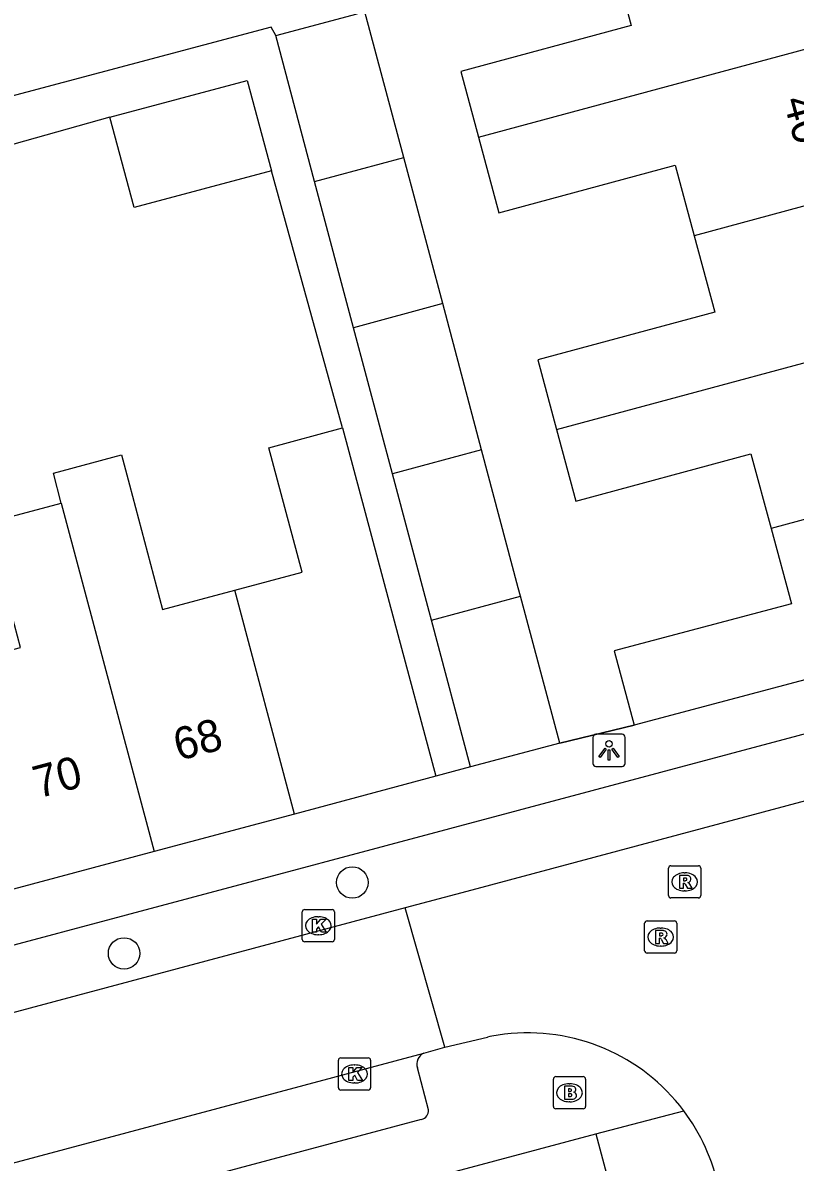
# Model space of a CAD drawing. Extents: x 162542 to 163144, y 380786 to 381511.
# Drawn here: x 162893.88 to 162917.88, y 381087.73 to 381123.11 of the extents above; entities that cross this region are included whole.
import ezdxf

# ---------------------------------------------------------------- set-up
doc = ezdxf.new("R2010")
doc.units = 0
for name, color, linetype in [('IMGEO_Boom', 7, 'Continuous'), ('IMGEO_Brandkraan', 7, 'Continuous'), ('IMGEO_Kolk', 7, 'Continuous'), ('IMGEO_Lichtpunt', 7, 'Continuous'), ('IMGEO_Muur', 7, 'Continuous'), ('IMGEO_Pand', 7, 'Continuous'), ('IMGEO_Pand_nummerreeks', 7, 'Continuous'), ('IMGEO_Rijbaan_lokaal_open', 7, 'Continuous'), ('IMGEO_Rioolput', 7, 'Continuous'), ('IMGEO_Voetpad_open', 7, 'Continuous')]:
    doc.layers.add(name, color=color, linetype=linetype)

msp = doc.modelspace()

# ---------------------------------------------------------------- linework, layer by layer
at = {"layer": 'IMGEO_Boom'}
for centre in [(162904.119, 381096.414), (162897.031, 381094.211)]:
    msp.add_circle(centre, 0.489, dxfattribs=at)
at = {"layer": 'IMGEO_Brandkraan'}
for p, q in [((162910.364, 381089.46), (162910.364, 381090.312)), ((162910.439, 381090.386), (162911.291, 381090.386)), ((162911.365, 381090.312), (162911.365, 381089.46)), ((162910.852, 381090.166), (162910.877, 381090.166)), ((162910.875, 381089.606), (162910.85, 381089.606)), ((162911.291, 381089.386), (162910.439, 381089.386))]:
    msp.add_line(p, q, dxfattribs=at)
for points in [[(162910.364, 381089.46), (162910.364, 381090.312)], [(162910.439, 381090.386), (162911.291, 381090.386)], [(162911.365, 381090.312), (162911.365, 381089.46)], [(162910.712, 381090.086), (162910.712, 381089.686), (162910.925, 381089.686)], [(162910.943, 381090.086), (162910.712, 381090.086)], [(162910.891, 381090.005), (162910.837, 381090.005), (162910.837, 381089.929)], [(162910.837, 381089.929), (162910.89, 381089.929)], [(162910.899, 381089.853), (162910.837, 381089.853), (162910.837, 381089.772)], [(162910.837, 381089.772), (162910.899, 381089.772)], [(162911.291, 381089.386), (162910.439, 381089.386)]]:
    msp.add_lwpolyline(points, dxfattribs=at)
for centre, radius, start, end in [((162910.441, 381090.31), 0.0765, 91.552, 178.448), ((162910.441, 381090.31), 0.0765, 91.552, 178.448), ((162911.289, 381090.31), 0.0765, 1.552, 88.448), ((162911.289, 381090.31), 0.0765, 1.552, 88.448), ((162910.892, 381089.967), 0.0379, 267.8285, 90.9355), ((162910.947, 381089.941), 0.145, 59.4692, 91.5367), ((162910.972, 381089.988), 0.0922, 285.5137, 58.1501), ((162910.9, 381089.812), 0.0404, 269.8759, 90.5077), ((162910.931, 381089.937), 0.251, 268.6676, 293.5347), ((162910.977, 381089.796), 0.105, 301.3115, 78.989), ((162910.441, 381089.462), 0.0765, 181.552, 268.448), ((162910.441, 381089.462), 0.0765, 181.552, 268.448), ((162911.289, 381089.462), 0.0765, 271.552, 358.448), ((162911.289, 381089.462), 0.0765, 271.552, 358.448)]:
    msp.add_arc(centre, radius, start, end, dxfattribs=at)
for centre, major_axis, ratio, start_param, end_param in [((162910.851, 381089.886), (-0.387, 0.002), 0.722429, 4.712389, 7.853982), ((162910.876, 381089.886), (-0.39, 0.002), 0.717154, 1.570796, 4.712389)]:
    msp.add_ellipse(centre, major_axis=major_axis, ratio=ratio, start_param=start_param, end_param=end_param, dxfattribs=at)
at = {"layer": 'IMGEO_Kolk'}
for p, q in [((162902.565, 381094.647), (162902.565, 381095.499)), ((162902.64, 381095.573), (162903.492, 381095.573)), ((162903.053, 381095.353), (162903.078, 381095.353)), ((162903.566, 381095.499), (162903.566, 381094.647)), ((162903.492, 381094.573), (162902.64, 381094.573)), ((162903.076, 381094.793), (162903.051, 381094.793)), ((162903.688, 381090.043), (162903.688, 381090.895)), ((162903.763, 381090.969), (162904.615, 381090.969)), ((162904.176, 381090.749), (162904.201, 381090.749)), ((162904.689, 381090.895), (162904.689, 381090.043)), ((162904.615, 381089.969), (162903.763, 381089.969)), ((162904.199, 381090.189), (162904.174, 381090.189))]:
    msp.add_line(p, q, dxfattribs=at)
for points in [[(162902.565, 381094.647), (162902.565, 381095.499)], [(162902.64, 381095.573), (162903.492, 381095.573)], [(162902.886, 381095.273), (162903.009, 381095.273), (162903.009, 381095.122), (162903.139, 381095.273), (162903.303, 381095.273), (162903.157, 381095.122), (162903.31, 381094.873), (162903.158, 381094.873), (162903.073, 381095.037), (162903.009, 381094.97), (162903.009, 381094.873), (162902.886, 381094.873), (162902.886, 381095.273)], [(162903.566, 381095.499), (162903.566, 381094.647)], [(162903.492, 381094.573), (162902.64, 381094.573)], [(162903.688, 381090.043), (162903.688, 381090.895)], [(162903.763, 381090.969), (162904.615, 381090.969)], [(162904.009, 381090.669), (162904.132, 381090.669), (162904.132, 381090.518), (162904.262, 381090.669), (162904.426, 381090.669), (162904.28, 381090.518), (162904.433, 381090.269), (162904.281, 381090.269), (162904.196, 381090.433), (162904.132, 381090.366), (162904.132, 381090.269), (162904.009, 381090.269), (162904.009, 381090.669)], [(162904.689, 381090.895), (162904.689, 381090.043)], [(162904.615, 381089.969), (162903.763, 381089.969)]]:
    msp.add_lwpolyline(points, dxfattribs=at)
for centre, start, end in [((162902.642, 381095.497), 91.552, 178.448), ((162902.642, 381095.497), 91.552, 178.448), ((162903.49, 381095.497), 1.552, 88.448), ((162903.49, 381095.497), 1.552, 88.448), ((162902.642, 381094.649), 181.552, 268.448), ((162902.642, 381094.649), 181.552, 268.448), ((162903.49, 381094.649), 271.552, 358.448), ((162903.49, 381094.649), 271.552, 358.448), ((162903.765, 381090.893), 91.552, 178.448), ((162903.765, 381090.893), 91.552, 178.448), ((162904.613, 381090.893), 1.552, 88.448), ((162904.613, 381090.893), 1.552, 88.448), ((162903.765, 381090.045), 181.552, 268.448), ((162903.765, 381090.045), 181.552, 268.448), ((162904.613, 381090.045), 271.552, 358.448), ((162904.613, 381090.045), 271.552, 358.448)]:
    msp.add_arc(centre, 0.0765, start, end, dxfattribs=at)
for centre, major_axis, ratio, start_param, end_param in [((162903.052, 381095.073), (-0.387, 0.002), 0.722429, 4.712389, 7.853982), ((162903.077, 381095.073), (-0.39, 0.002), 0.717154, 1.570796, 4.712389), ((162904.175, 381090.469), (-0.387, 0.002), 0.722429, 4.712389, 7.853982), ((162904.2, 381090.469), (-0.39, 0.002), 0.717154, 1.570796, 4.712389)]:
    msp.add_ellipse(centre, major_axis=major_axis, ratio=ratio, start_param=start_param, end_param=end_param, dxfattribs=at)
at = {"layer": 'IMGEO_Lichtpunt'}
for p, q in [((162911.594, 381100.921), (162911.594, 381100.114)), ((162911.594, 381100.921), (162911.594, 381100.114)), ((162912.496, 381101.016), (162911.688, 381101.016)), ((162912.496, 381101.016), (162911.688, 381101.016)), ((162912.59, 381100.114), (162912.59, 381100.921)), ((162912.59, 381100.114), (162912.59, 381100.921)), ((162911.688, 381100.02), (162912.496, 381100.02)), ((162911.688, 381100.02), (162912.496, 381100.02))]:
    msp.add_line(p, q, dxfattribs=at)
for points in [[(162911.968, 381100.585), (162912.007, 381100.557), (162911.819, 381100.295), (162911.781, 381100.322), (162911.968, 381100.585)], [(162912.18, 381100.557), (162912.218, 381100.584), (162912.405, 381100.322), (162912.366, 381100.294), (162912.18, 381100.557)], [(162912.07, 381100.537), (162912.117, 381100.537), (162912.117, 381100.215), (162912.07, 381100.215), (162912.07, 381100.537)]]:
    msp.add_lwpolyline(points, dxfattribs=at)
msp.add_circle((162912.093, 381100.719), 0.0994, dxfattribs=at)
for centre, start, end in [((162911.688, 381100.921), 90, 180), ((162911.688, 381100.921), 90, 180), ((162912.496, 381100.921), 0, 90), ((162912.496, 381100.921), 0, 90), ((162911.688, 381100.114), 180, 270), ((162911.688, 381100.114), 180, 270), ((162912.496, 381100.114), 270, 0), ((162912.496, 381100.114), 270, 360)]:
    msp.add_arc(centre, 0.0946, start, end, dxfattribs=at)
at = {"layer": 'IMGEO_Muur'}
msp.add_lwpolyline([(162910.56, 381100.744), (162912.873, 381101.295)], dxfattribs=at)
at = {"layer": 'IMGEO_Pand'}
for points in [[(162912.087, 381125.607), (162912.783, 381123.027), (162907.49, 381121.599), (162908.042, 381119.555)], [(162901.741, 381122.714), (162904.267, 381123.387)], [(162905.717, 381118.928), (162904.512, 381123.452), (162904.267, 381123.387)], [(162902.948, 381118.181), (162901.741, 381122.714)], [(162908.042, 381119.555), (162920.256, 381122.851)], [(162896.588, 381120.178), (162900.859, 381121.319), (162901.61, 381118.51)], [(162901.61, 381118.51), (162897.339, 381117.369), (162896.588, 381120.178)], [(162908.042, 381119.555), (162908.674, 381117.211), (162914.145, 381118.687), (162914.736, 381116.495)], [(162902.948, 381118.181), (162905.717, 381118.928)], [(162906.926, 381114.388), (162905.717, 381118.928)], [(162921.471, 381118.312), (162914.736, 381116.495)], [(162904.158, 381113.641), (162902.948, 381118.181)], [(162914.736, 381116.495), (162915.375, 381114.126), (162909.881, 381112.644), (162910.466, 381110.476)], [(162906.926, 381114.388), (162904.158, 381113.641)], [(162908.136, 381109.847), (162906.926, 381114.388)], [(162910.466, 381110.476), (162922.685, 381113.774)], [(162905.367, 381109.1), (162904.158, 381113.641)], [(162900.475, 381105.495), (162902.557, 381106.051), (162901.525, 381109.915), (162903.813, 381110.528)], [(162903.813, 381110.528), (162905.419, 381104.542), (162906.714, 381099.712)], [(162910.466, 381110.476), (162911.065, 381108.254), (162916.502, 381109.721), (162917.127, 381107.407)], [(162908.136, 381109.847), (162905.367, 381109.1)], [(162909.345, 381105.308), (162909.275, 381105.569), (162908.136, 381109.847)], [(162895.082, 381108.194), (162894.834, 381109.127), (162896.948, 381109.69), (162897.197, 381108.759), (162898.229, 381104.895), (162900.475, 381105.495)], [(162906.576, 381104.561), (162906.504, 381104.831), (162905.367, 381109.1)], [(162923.9, 381109.234), (162917.127, 381107.407)], [(162891.746, 381103.164), (162893.813, 381103.716), (162892.781, 381107.58), (162895.082, 381108.194)], [(162895.082, 381108.194), (162897.964, 381097.375)], [(162917.127, 381107.407), (162917.759, 381105.065), (162912.25, 381103.604), (162912.873, 381101.295)], [(162902.328, 381098.541), (162900.475, 381105.495)], [(162906.576, 381104.561), (162909.345, 381105.308)], [(162910.56, 381100.744), (162909.345, 381105.308)], [(162907.791, 381100.001), (162906.576, 381104.561)], [(162925.15, 381104.562), (162912.873, 381101.295)], [(162910.56, 381100.744), (162907.791, 381100.001)], [(162906.714, 381099.712), (162902.328, 381098.541)], [(162902.328, 381098.541), (162897.964, 381097.375)], [(162897.964, 381097.375), (162893.599, 381096.209)], [(162907.185, 381087.409), (162909.899, 381088.134), (162911.688, 381088.611)], [(162911.688, 381088.611), (162914.576, 381077.79), (162915.089, 381075.867)]]:
    msp.add_lwpolyline(points, dxfattribs=at)
at = {"layer": 'IMGEO_Rijbaan_lokaal_open'}
for points in [[(162901.741, 381122.714), (162901.595, 381122.971), (162820.992, 381101.538), (162820.968, 381101.532)], [(162922.875, 381100.201), (162907.674, 381096.138), (162905.759, 381095.626)], [(162905.759, 381095.626), (162875.371, 381087.503), (162868.302, 381085.609)], [(162906.998, 381091.296), (162905.759, 381095.626)], [(162906.998, 381091.296), (162908.323, 381091.615)], [(162871.254, 381081.738), (162906.341, 381091.119)], [(162906.341, 381091.119), (162906.488, 381091.158), (162906.998, 381091.296)]]:
    msp.add_lwpolyline(points, dxfattribs=at)
for centre, radius, start, end in [((162909.574, 381085.696), 6.05, 36.8734, 96.8935), ((162909.636, 381085.321), 6.43, 97.0376, 101.7809), ((162909.561, 381085.69), 6.064, 11.7881, 36.8402)]:
    msp.add_arc(centre, radius, start, end, dxfattribs=at)
at = {"layer": 'IMGEO_Rioolput'}
for p, q in [((162913.942, 381096.007), (162913.942, 381096.859)), ((162914.017, 381096.933), (162914.869, 381096.933)), ((162914.43, 381096.713), (162914.455, 381096.713)), ((162914.943, 381096.859), (162914.943, 381096.007)), ((162914.453, 381096.153), (162914.428, 381096.153)), ((162914.869, 381095.933), (162914.017, 381095.933)), ((162913.198, 381094.295), (162913.198, 381095.147)), ((162913.273, 381095.221), (162914.125, 381095.221)), ((162913.686, 381095.001), (162913.711, 381095.001)), ((162914.199, 381095.147), (162914.199, 381094.295)), ((162914.125, 381094.221), (162913.273, 381094.221)), ((162913.709, 381094.441), (162913.684, 381094.441))]:
    msp.add_line(p, q, dxfattribs=at)
for points in [[(162913.942, 381096.007), (162913.942, 381096.859)], [(162914.017, 381096.933), (162914.869, 381096.933)], [(162914.943, 381096.859), (162914.943, 381096.007)], [(162914.531, 381096.631), (162914.279, 381096.633), (162914.279, 381096.233)], [(162914.279, 381096.233), (162914.403, 381096.233), (162914.403, 381096.395), (162914.414, 381096.395)], [(162914.457, 381096.552), (162914.403, 381096.552), (162914.403, 381096.471)], [(162914.403, 381096.471), (162914.455, 381096.471)], [(162914.461, 381096.366), (162914.532, 381096.233), (162914.672, 381096.233), (162914.607, 381096.359)], [(162914.869, 381095.933), (162914.017, 381095.933)], [(162913.198, 381094.295), (162913.198, 381095.147)], [(162913.273, 381095.221), (162914.125, 381095.221)], [(162913.787, 381094.919), (162913.535, 381094.921), (162913.535, 381094.521)], [(162914.199, 381095.147), (162914.199, 381094.295)], [(162913.535, 381094.521), (162913.659, 381094.521), (162913.659, 381094.683), (162913.67, 381094.683)], [(162913.713, 381094.84), (162913.659, 381094.84), (162913.659, 381094.759)], [(162913.659, 381094.759), (162913.711, 381094.759)], [(162913.717, 381094.654), (162913.788, 381094.521), (162913.928, 381094.521), (162913.863, 381094.647)], [(162914.125, 381094.221), (162913.273, 381094.221)]]:
    msp.add_lwpolyline(points, dxfattribs=at)
for centre, radius, start, end in [((162914.019, 381096.857), 0.0765, 91.552, 178.448), ((162914.019, 381096.857), 0.0765, 91.552, 178.448), ((162914.867, 381096.857), 0.0765, 1.552, 88.448), ((162914.867, 381096.857), 0.0765, 1.552, 88.448), ((162914.413, 381096.342), 0.0533, 26.0293, 88.6989), ((162914.439, 381096.66), 0.19, 274.7715, 282.9687), ((162914.463, 381096.456), 0.0964, 77.0061, 93.1865), ((162914.477, 381096.513), 0.0378, 276.6634, 79.6772), ((162914.53, 381096.521), 0.109, 350.3612, 89.416), ((162914.528, 381096.521), 0.112, 277.5842, 350.9817), ((162914.512, 381096.306), 0.108, 29.5134, 73.7905), ((162914.019, 381096.009), 0.0765, 181.552, 268.448), ((162914.019, 381096.009), 0.0765, 181.552, 268.448), ((162914.867, 381096.009), 0.0765, 271.552, 358.448), ((162914.867, 381096.009), 0.0765, 271.552, 358.448), ((162913.275, 381095.145), 0.0765, 91.552, 178.448), ((162913.275, 381095.145), 0.0765, 91.552, 178.448), ((162913.786, 381094.809), 0.109, 350.3612, 89.416), ((162914.123, 381095.145), 0.0765, 1.552, 88.448), ((162914.123, 381095.145), 0.0765, 1.552, 88.448), ((162913.669, 381094.63), 0.0533, 26.0293, 88.6989), ((162913.695, 381094.948), 0.19, 274.7715, 282.9687), ((162913.719, 381094.744), 0.0964, 77.0061, 93.1865), ((162913.733, 381094.801), 0.0378, 276.6634, 79.6772), ((162913.784, 381094.809), 0.112, 277.5842, 350.9817), ((162913.768, 381094.594), 0.108, 29.5134, 73.7905), ((162913.275, 381094.297), 0.0765, 181.552, 268.448), ((162913.275, 381094.297), 0.0765, 181.552, 268.448), ((162914.123, 381094.297), 0.0765, 271.552, 358.448), ((162914.123, 381094.297), 0.0765, 271.552, 358.448)]:
    msp.add_arc(centre, radius, start, end, dxfattribs=at)
for centre, major_axis, ratio, start_param, end_param in [((162914.429, 381096.433), (-0.387, 0.002), 0.722429, 4.712389, 7.853982), ((162914.454, 381096.433), (-0.39, 0.002), 0.717154, 1.570796, 4.712389), ((162913.685, 381094.721), (-0.387, 0.002), 0.722429, 4.712389, 7.853982), ((162913.71, 381094.721), (-0.39, 0.002), 0.717154, 1.570796, 4.712389)]:
    msp.add_ellipse(centre, major_axis=major_axis, ratio=ratio, start_param=start_param, end_param=end_param, dxfattribs=at)
at = {"layer": 'IMGEO_Voetpad_open'}
for points in [[(162896.588, 381120.178), (162882.812, 381116.307)], [(162903.813, 381110.528), (162901.61, 381118.51)], [(162829.44, 381077.293), (162857.097, 381084.74), (162857.529, 381083.089), (162861.656, 381084.179), (162861.251, 381085.851), (162866.655, 381087.296), (162874.876, 381089.481), (162907.148, 381098.095), (162922.391, 381102.163), (162922.875, 381100.201)], [(162912.873, 381101.295), (162910.56, 381100.744)], [(162907.791, 381100.001), (162906.714, 381099.712)], [(162906.484, 381089.358), (162906.142, 381090.654)], [(162911.688, 381088.611), (162914.414, 381089.326)], [(162872.337, 381079.995), (162906.267, 381089.06)]]:
    msp.add_lwpolyline(points, dxfattribs=at)
for centre, radius, start, end in [((162906.514, 381090.77), 0.39, 116.3668, 197.2955), ((162906.216, 381089.325), 0.27, 280.9696, 6.9071)]:
    msp.add_arc(centre, radius, start, end, dxfattribs=at)

# ---------------------------------------------------------------- texts
at = {"layer": 'IMGEO_Pand_nummerreeks'}
for s, rotation, p in [('40', 285.0989, (162917.5, 381120.702)), ('68', 14.9542, (162898.724, 381100.187)), ('70', 14.9536, (162894.362, 381099.021))]:
    msp.add_text(s, height=1, rotation=rotation, dxfattribs=at).set_placement(p)

doc.saveas('drawing.dxf')
